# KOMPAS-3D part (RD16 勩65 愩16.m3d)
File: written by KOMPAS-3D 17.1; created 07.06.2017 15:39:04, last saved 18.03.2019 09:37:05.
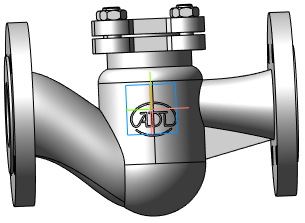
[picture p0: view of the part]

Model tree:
1. Операция без истории:2  (labels: Сталь 20  ГОСТ 1050-88)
